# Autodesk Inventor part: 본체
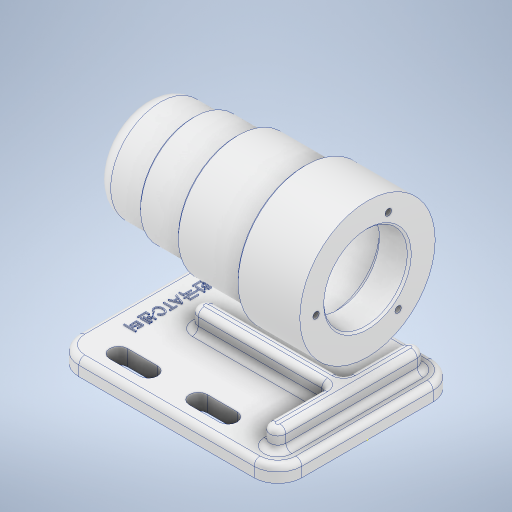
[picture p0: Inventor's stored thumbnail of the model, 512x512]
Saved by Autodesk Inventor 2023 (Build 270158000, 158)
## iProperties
Created: 2022-07
Part Number: 본체
Material: 알루미늄 6061
Document SubType Name: Modeling
Designer: owner
Density: 2.7 g/cm^3
Appearance: 알루미늄 - 평지
Author: owner
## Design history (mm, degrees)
sketch "스케치1"
  geometry: L1 (56, -45)-(-56, -45); L2 (-56, -45)-(-56, 45); L3 (-56, 45)-(56, 45); L4 (56, 45)-(56, -45); L5 (56, -45)-(-56, 45); L6 (-56, -45)-(56, 45); L7 (56, 0)-(-56, 0); L8 (36, -33)-(21, -33); L9 (36, -28.5)-(21, -28.5); L10 (21, -37.5)-(36, -37.5); L11 (-4, -33)-(-19, -33); L12 (-4, -28.5)-(-19, -28.5); L13 (-19, -37.5)-(-4, -37.5); L14 (36, 28.5)-(21, 28.5); L15 (21, 37.5)-(36, 37.5); L16 (-19, 37.5)-(-4, 37.5); L17 (-4, 28.5)-(-19, 28.5); A1 r 4.5 centre (36, -33) between (36, -37.5) and (36, -28.5); A2 r 4.5 centre (21, -33) between (21, -28.5) and (21, -37.5); A3 r 4.5 centre (-4, -33) between (-4, -37.5) and (-4, -28.5); A4 r 4.5 centre (-19, -33) between (-19, -28.5) and (-19, -37.5); A5 r 4.5 centre (21, 33) between (21, 37.5) and (21, 28.5); A6 r 4.5 centre (36, 33) between (36, 28.5) and (36, 37.5); A7 r 4.5 centre (-4, 33) between (-4, 28.5) and (-4, 37.5); A8 r 4.5 centre (-19, 33) between (-19, 37.5) and (-19, 28.5); 3 further points
  constraints: 38 end point, 16 point on circle, 12 symmetric about line, 8 centre point, 8 tangent, 6 midpoint, 5 parallel, 2 horizontal, 1 horizontal alignment, 1 perpendicular, 4 other
  dimensions: "d0" = 112 distance of L2.end L3.end; "d1" = 90 distance of L1.end L2.end; "d2" = 9 diameter of A4; "d3" = 9 distance between parallel lines of L9 L10; "d4" = 15 distance of L8.end L8.start; "d5" = 15 distance of L11.end L11.start; "d6" = 20 distance from line of L4 L8.start; "d7" = 25 distance of L11.start L8.end; "d8" = 33 distance between parallel lines of L7 L11
extrude "돌출1" new body sketch "스케치1" distance "d9" = 8; taper "d10" = 0 deg
sketch "스케치2"
  geometry: L1 (-56, 8)-(56, 8) reference; L2 (-56, 0)-(-56, 8) reference; L3 (56, 104)-(25, 104); L4 (24, 103)-(24, 100); L5 (24, 100)-(-9, 100); L6 (-10, 99)-(-10, 97); L7 (-10, 97)-(-31, 97); L8 (-32, 96)-(-32, 95); L9 (-32, 95)-(-48, 95); L10 (-56, 87)-(-56, 70); L11 (56, 104)-(56, 92); L12 (-56, 70)-(56, 70); L13 (-56, 0)-(56, 0) reference; L14 (-31, 97)-(-32, 96); L15 (-9, 100)-(-10, 99); L16 (25, 104)-(24, 103); L17 (-25, 87.5)-(-43, 87.5); L18 (-43, 87.5)-(-43, 86); L19 (-43, 86)-(-45.057, 86); L20 (-45.057, 86)-(-45.057, 80.5); L21 (-45.057, 80.5)-(-46.5, 80.5); L22 (-49.5, 77.5)-(-49.5, 70); L23 (-25, 87.5)-(-25, 91); L24 (-25, 91)-(-13, 91); L25 (41, 91)-(41, 91); L26 (41, 91)-(55, 91); L27 (55, 91)-(56, 92); L28 (56, 92)-(56, 70); L29 (-13, 91)-(-13, 91); L30 (-10, 94)-(38, 94); A1 r 8 centre (-48, 87) between (-48, 95) and (-56, 87); A2 r 3 centre (-10, 91) between (-10, 94) and (-13, 91); A3 r 3 centre (38, 91) between (41, 91) and (38, 94); A4 r 3 centre (-46.5, 77.5) between (-46.5, 80.5) and (-49.5, 77.5); 10 further points
  constraints: 54 end point, 12 perpendicular, 12 point on line, 8 point on circle, 8 tangent, 4 centre point, 4 horizontal, 3 vertical, 2 equal radius, 2 midpoint
  dimensions: "d15" = 112 distance between parallel lines of L11 L10; "d16" = 50 diameter of L9 L12; "d17" = 54 diameter of L7 L12; "d18" = 60 diameter of L5 L12; "d19" = 68 diameter of L3 L12; "d20" = 8 radius of A1; "d21" = 24 distance between parallel lines of L8 L10; "d22" = 46 distance between parallel lines of L6 L10; "d23" = 80 distance between parallel lines of L4 L10; "d24" = 70 distance between parallel lines of L13 L12; "d25" = 1 distance of L7.end point (-32, 97); "d26" = 1 distance of L8.start point (-32, 97) (= d25); "d27" = 1 distance of L5.end point (-10, 100) (= d25); "d28" = 1 distance of L6.start point (-10, 100) (= d27); "d29" = 1 distance of L3.end point (24, 104) (= d25); "d30" = 1 distance of L4.start point (24, 104) (= d29); "d31" = 56 distance from line of L10 point (0, 0); "d32" = 21 diameter of L21 L12; "d33" = 32 diameter of L19 L12; "d34" = 35 diameter of L17 L12; "d35" = 42 diameter of L24 L12; "d37" = 42 diameter of L26 L12; "d41" = 1 distance of L26.end point (56, 91) (= d39); "d42" = 1 distance of L11.end point (56, 91) (= d41); "d45" = 15 distance between parallel lines of L11 L25; "d48" = 12 distance between parallel lines of L23 L29; "d52" = 18 distance of L17.end L17.start; "d53" = 24.5 distance between parallel lines of L23 L22; "d54" = 4.44268 distance between parallel lines of L20 L22; "d55" = 3 radius of A2; "d56" = 46 distance from line of L10 L30.start; "d57" = 48 diameter of L30 L12
revolve "회전1" sketch "스케치2" stored, may be unused: angle "d58" = 90 deg
sketch "스케치3"
  geometry: L1 (56, -45)-(56, 45) reference; L2 (-56, 45)-(-56, -45) reference; L3 (-56, -45)-(56, -45) reference; L4 (-56, 45)-(-56, -45) reference; L5 (56, 45)-(-56, 45) reference; L6 (56, -45)-(56, 45) reference; L7 (19, -37.5)-(4, -37.5) reference; L8 (4, -28.5)-(19, -28.5) reference; L9 (-21, -37.5)-(-36, -37.5) reference; L10 (-36, -28.5)-(-21, -28.5) reference; L11 (19, 28.5)-(4, 28.5) reference; L12 (4, 37.5)-(19, 37.5) reference; L13 (-21, 28.5)-(-36, 28.5) reference; L14 (-36, 37.5)-(-21, 37.5) reference; L15 (-25, 0)-(44, 0); L16 (-25, -4)-(44, -4); L17 (44, 4)-(-25, 4); L18 (44, 33)-(44, -33); L19 (40, 33)-(40, -33); L20 (48, -33)-(48, 33); L21 (-56, 0)-(56, 0); A1 r 4.5 centre (19, -33) between (19, -37.5) and (19, -28.5) reference; A2 r 4.5 centre (4, -33) between (4, -28.5) and (4, -37.5) reference; A3 r 4.5 centre (-21, -33) between (-21, -37.5) and (-21, -28.5) reference; A4 r 4.5 centre (-36, -33) between (-36, -28.5) and (-36, -37.5) reference; A5 r 4.5 centre (4, 33) between (4, 37.5) and (4, 28.5) reference; A6 r 4.5 centre (19, 33) between (19, 28.5) and (19, 37.5) reference; A7 r 4.5 centre (-36, 33) between (-36, 37.5) and (-36, 28.5) reference; A8 r 4.5 centre (-21, 33) between (-21, 28.5) and (-21, 37.5) reference; A9 r 4 centre (-25, 0) between (-25, 4) and (-25, -4); A10 r 4 centre (44, 0) between (44, -4) and (44, 4); A11 r 4 centre (44, 33) between (48, 33) and (40, 33); A12 r 4 centre (44, -33) between (40, -33) and (48, -33); 7 further points
  constraints: 18 end point, 9 point on circle, 8 tangent, 6 midpoint, 4 centre point, 2 parallel, 1 horizontal, 1 perpendicular, 1 point on line, 1 vertical
  dimensions: "d81" = 8 distance between parallel lines of L20 L19; "d82" = 8 distance between parallel lines of L16 L17; "d83" = 77 distance from line of L20 point (-29, 0); "d84" = 8 distance between parallel lines of L1 L20; "d85" = 33 distance from line of L18.end L21; "d86" = 66 distance of L18.end L18.start
extrude "돌출2" join sketch "스케치3" distance "d69" = 10; taper "d70" = 0 deg
sketch "스케치8"
  geometry: 1 further point
sketch "스케치9"
  geometry: C1 r 7.5 at (0, 0) reference; A1 r 26 centre (0, 0) between (-25.844, -2.842) and (15.383, -20.961); 3 further points
  constraints: 2 point on circle, 1 centre point, 1 coincident, 2 other
  dimensions: "d94" = 52 diameter of A1; "d95" = 120 deg dimension on A1.centre A1.start point (10.461, 23.803); "d96" = 120 deg dimension on A1.centre A1.end A1.start
hole "구멍1" sketch "스케치9" at (10.461, 23.803), (-25.844, -2.842), (15.383, -20.961) diameter "d97" = 3.242; stored, may be unused: countersink angle "d101" = 90 deg, drill point angle "d103" = 118 deg; dims "d98" = 8, "d99" = 4, "d100" = 2, "d102" = 11
fillet "모깎기1" dims "d104" = 12
fillet "모깎기2" dims "d105" = 3
sketch "스케치10"
  geometry: L1 (-36, -28.5)-(-21, -28.5) reference; L2 (-56, 33)-(-56, -33) reference; A1 r 4.5 centre (-36, -33) between (-36, -28.5) and (-36, -37.5) reference; 2 further points
  constraints: 1 other
  dimensions: "d106" = 33 vertical distance of point (-44, 0) A1.centre; "d107" = 12 distance from line of point (-44, 0) L2
feature "엠보싱1" sketch "스케치10" dims "d0" = 112, "d1" = 90, "d2" = 9, "d3" = 9, "d4" = 15, "d5" = 15, "d6" = 20, "d7" = 25, "d8" = 33, "d108" = 0.5, "d109" = 0
node "솔리드1"
node "투영된 루프1"
feature "A9D066F2-1C7D-4E18-AEED-F7BC21143FA4" dims "d97" = 3.242, "d98" = 8, "d99" = 4, "d100" = 2, "d101" = 90 deg, "d102" = 11, "d103" = 118 deg
other parameters: "d39" = 1, "d65" = 8
